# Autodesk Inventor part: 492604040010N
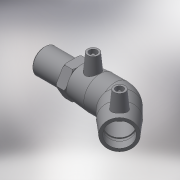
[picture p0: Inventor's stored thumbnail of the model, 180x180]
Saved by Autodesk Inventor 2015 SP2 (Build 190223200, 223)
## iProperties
Created: 2017-06
Part Number: 492604040010N
Material: Generic
Description: PLASSON 45° ELBOW TRANSITION MALE 40 x 1"
Document SubType Name: Modeling
Designer: KIM
Mass: 218.677 g
Surface Area: 482.454 cm^2
Volume: 218.677 cm^3
Density: 1 g/cm^3
Appearance: Default
Author: KIM
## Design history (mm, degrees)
derived "492604.ipt"
feature "Solid1::492604.ipt"
tag "TaggingFeature1"
body "Solid1"
other parameters: "d2" = 56, "d4" = 28.25, "d5" = 50.4, "d8" = 168 deg, "d10" = 19.2, "d11" = 6.4, "d29" = 47, "d30" = 15, "d31" = 39.55, "d34" = 5 deg, "d41" = 4, "d42" = 14, "d43" = 0, "d50" = 26, "d51" = 19.2, "d52" = 49.44, "d54" = 135 deg, "d86" = 25.2, "d87" = 135 deg, "d88" = 113, "d90" = 48, "d91" = 0, "d92" = 48, "d93" = 0, "d101" = 3, "d102" = 0, "d107" = 0.1, "d108" = 22, "d109" = 33.249, "d110" = 45, "d111" = 11.25, "d112" = 56, "d113" = 23.2743, "d114" = 40.5, "d116" = 1.68, "d122" = 0, "d123" = 1.66245, "L_" = 158, "L_1" = 48, "D_" = 22, "A_" = 47, "d_2" = 12, "L_2" = 45, "R_" = 33.249, "D_1" = 56
